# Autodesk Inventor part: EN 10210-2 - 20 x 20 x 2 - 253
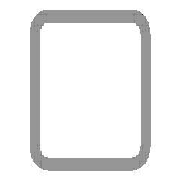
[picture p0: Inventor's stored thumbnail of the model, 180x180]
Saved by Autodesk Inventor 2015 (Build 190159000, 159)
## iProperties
Created: 2015-05
Part Number: EN 10210-2 - 20 x 20 x 2 - 253
Material: Steel, Mild
Description: Tube
Document SubType Name: Modeling
Standard: DIN
Designer: TREINA6
Standard Revision: 1997
Standards Organization: DIN
Language: en-US
Size Designation: 20 x 20 x 2
Categories: <MemberInstance><Categories><Category DisplayName="Structural Shapes" InternalName="089c4875-fa83-4c05-b084-43b9cc11f5ed" Mnemonic="GRDR"><CategoryParameter Dis
Stock Number: 20 x 20 x 2
Density: 7.85 g/cm^3
Appearance: Semi-Polished
_CCFamilyMember: 1
_CCFamilyDisplayName: DIN EN 10210-2 (Square) - Tube
_FrameMemberDoc: Frame Member File
_Version: 15.0.0
_GetPNFromCC: 1
IsCustomPart: 1
Author: TREINA6
G_L: 253,000 mm
G_W: 20,000 mm
G_H: 20,000 mm
+AC749DCF-2404-4771-B15D-8F815B6C9E4F+CUTDETAIL1: Miter 45,00 deg
+2BFCD211-69C8-43B1-8338-467FB59833FA+CUTDETAIL2: Miter 45,00 deg
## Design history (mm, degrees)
node "Start plane"
node "End plane"
sketch "Sketch"
  geometry: L1 (-10, -7)-(-10, 7); L2 (-7, 10)-(7, 10); L3 (10, 7)-(10, -7); L4 (7, -10)-(-7, -10); L5 (-7, 8)-(7, 8); L6 (8, 7)-(8, -7); L7 (7, -8)-(-7, -8); L8 (-8, -7)-(-8, 7); L9 (0, 14.87)-(0, -14.87) reference; L10 (-14.87, 0)-(14.87, 0) reference; A1 r 3 centre (-7, -7) between (-10, -7) and (-7, -10); A2 r 3 centre (-7, 7) between (-7, 10) and (-10, 7); A3 r 3 centre (7, 7) between (10, 7) and (7, 10); A4 r 3 centre (7, -7) between (7, -10) and (10, -7); A5 r 1 centre (-7, 7) between (-7, 8) and (-8, 7); A6 r 1 centre (7, 7) between (8, 7) and (7, 8); A7 r 1 centre (7, -7) between (7, -8) and (8, -7); A8 r 1 centre (-7, -7) between (-8, -7) and (-7, -8)
  constraints: 16 end point, 16 point on circle, 8 centre point, 8 tangent, 4 parallel, 3 equal radius, 2 perpendicular, 7 other
  dimensions: "d7" = 3 radius of A1 (= G_IR); "d10" = 20 distance between parallel lines of L2 L4 (= G_H); "d11" = 20 distance between parallel lines of L1 L3 (= G_W); "d12" = 2 distance between parallel lines of L3 L6 (= G_T); "d15" = 10 distance between parallel lines of L2 L10 (= 0.5 x d10); "d16" = 10 distance between parallel lines of L9 L3 (= 0.5 x d11)
extrude "Body" new body sketch "Sketch" stored distance "d3" = 253 (= G_L); taper "d4" = 0 deg
node "Driven Length"
  sketch "Sketch3"
    geometry: L1 (0, 0)-(10, 0) reference
    constraints: 2 end point, 1 horizontal
  workplane "Work Plane3"
  sketch "Sketch4"
    geometry: L1 (-2, 0)-(12, 0) reference; L2 (-2, 253)-(12, 253) reference
    dimensions: "d18" = 253 distance between parallel lines of L1 L2 (derived)
workplane "Work Plane4"
split "Split1"
workplane "Work Plane5"
split "Split2"
body "Solid1"
other parameters: "G_W" = 20 [user parameter; used in 1 equation term], "G_H" = 20 [user parameter; used in 1 equation term], "G_T" = 2 [user parameter; used in 1 equation term], "G_IR" = 3 [user parameter; used in 1 equation term], "G_L" = 253 (= d18) [user parameter; used in 1 equation term], "G_OFFSET_START" = 0 [user parameter; used in 1 equation term], "G_OFFSET_END" = 0 [user parameter; used in 1 equation term], "d13" = 0 (computed from G_OFFSET_START), "d14" = 253 (= G_OFFSET_END + B_L), "B_L" = 253 [user parameter; used in 1 equation term], "d17" = 90 deg
